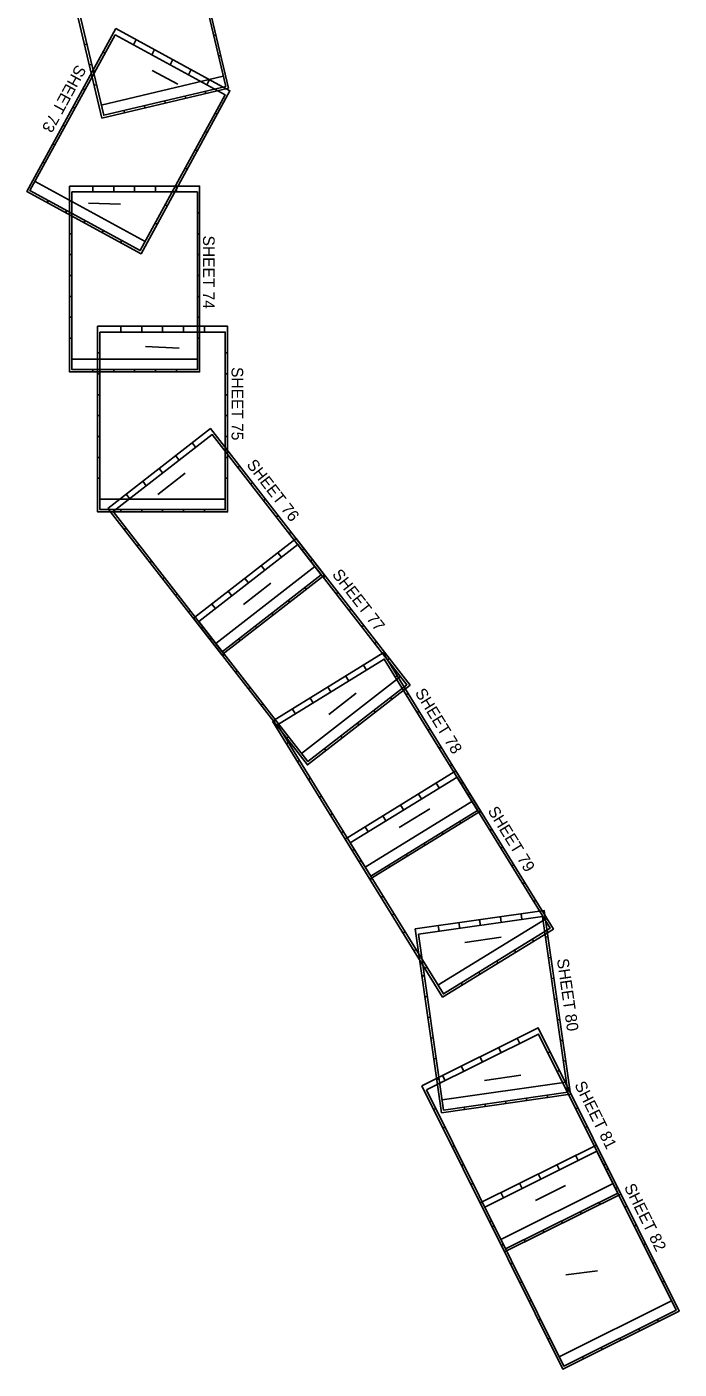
# Model space of a CAD drawing. Extents: x 518852 to 589310, y 1937169 to 2155394.
# Drawn here: x 575262 to 589310, y 1937169 to 1966083 of the extents above; entities that cross this region are included whole.
import ezdxf

# ---------------------------------------------------------------- set-up
doc = ezdxf.new("R2010")
doc.units = 0
doc.layers.add('Level 1', color=7, linetype='Continuous')
doc.layers.add('Level 58', color=7, linetype='Continuous')

msp = doc.modelspace()

# ---------------------------------------------------------------- linework, layer by layer
at = {"layer": 'Level 1'}
for p, q in [((579285, 1965896), (579334, 1965907)), ((576505, 1965700), (576554, 1965711)), ((577556, 1965698), (577616, 1965808)), ((576901, 1965542), (576945, 1965518)), ((577951, 1965483), (578011, 1965593)), ((578346, 1965267), (578406, 1965377)), ((579389, 1965458), (579437, 1965469)), ((576609, 1965262), (576658, 1965273)), ((576686, 1965147), (576730, 1965123)), ((578741, 1965052), (578801, 1965162)), ((576471, 1964752), (576515, 1964728)), ((576713, 1964824), (576761, 1964835)), ((579492, 1965020), (576865, 1964398)), ((579136, 1964837), (579196, 1964947)), ((578242, 1964441), (578231, 1964490)), ((578680, 1964545), (578669, 1964594)), ((579118, 1964649), (579106, 1964697)), ((576255, 1964357), (576299, 1964333)), ((577366, 1964234), (577355, 1964282)), ((577804, 1964337), (577793, 1964386)), ((579316, 1964226), (579360, 1964202)), ((576040, 1963962), (576084, 1963938)), ((579101, 1963831), (579145, 1963807)), ((575825, 1963567), (575869, 1963543)), ((578885, 1963436), (578929, 1963412)), ((575609, 1963172), (575653, 1963148)), ((578670, 1963041), (578714, 1963017)), ((577809, 1961460), (575438, 1962753)), ((576684, 1962527), (576684, 1962652)), ((577134, 1962527), (577134, 1962652)), ((577584, 1962527), (577584, 1962652)), ((578034, 1962527), (578034, 1962652)), ((578455, 1962646), (578499, 1962622)), ((578484, 1962527), (578484, 1962652)), ((575701, 1962296), (575725, 1962340)), ((578239, 1962251), (578283, 1962227)), ((576096, 1962080), (576120, 1962124)), ((576184, 1962077), (576234, 1962077)), ((576492, 1961865), (576515, 1961909)), ((578024, 1961856), (578068, 1961832)), ((578934, 1962077), (578984, 1962077)), ((576184, 1961627), (576234, 1961627)), ((576887, 1961650), (576911, 1961694)), ((578934, 1961627), (578984, 1961627)), ((577282, 1961434), (577306, 1961478)), ((576184, 1961177), (576234, 1961177)), ((578934, 1961177), (578984, 1961177)), ((576184, 1960727), (576234, 1960727)), ((578934, 1960727), (578984, 1960727)), ((576184, 1960277), (576234, 1960277)), ((578934, 1960277), (578984, 1960277)), ((576184, 1959827), (576234, 1959827)), ((578934, 1959827), (578984, 1959827)), ((577286, 1959510), (577286, 1959635)), ((577736, 1959510), (577736, 1959635)), ((578186, 1959510), (578186, 1959635)), ((578636, 1959510), (578636, 1959635)), ((579086, 1959510), (579086, 1959635)), ((576184, 1959377), (576234, 1959377)), ((578934, 1959377), (578984, 1959377)), ((576786, 1959060), (576836, 1959060)), ((579536, 1959060), (579586, 1959060)), ((578934, 1958927), (576234, 1958927)), ((576684, 1958652), (576684, 1958702)), ((577134, 1958652), (577134, 1958702)), ((577584, 1958652), (577584, 1958702)), ((578034, 1958652), (578034, 1958702)), ((578484, 1958652), (578484, 1958702)), ((576786, 1958610), (576836, 1958610)), ((579536, 1958610), (579586, 1958610)), ((576786, 1958160), (576836, 1958160)), ((579536, 1958160), (579586, 1958160)), ((576786, 1957710), (576836, 1957710)), ((579536, 1957710), (579586, 1957710)), ((576786, 1957260), (576836, 1957260)), ((579536, 1957260), (579586, 1957260)), ((578899, 1957024), (578823, 1957123)), ((579531, 1956945), (579570, 1956976)), ((576786, 1956810), (576836, 1956810)), ((578544, 1956748), (578467, 1956847)), ((579536, 1956810), (579586, 1956810)), ((576786, 1956360), (576836, 1956360)), ((578189, 1956472), (578112, 1956571)), ((579536, 1956360), (579586, 1956360)), ((579807, 1956590), (579846, 1956621)), ((577833, 1956196), (577757, 1956294)), ((580083, 1956235), (580123, 1956265)), ((579536, 1955910), (576836, 1955910)), ((577478, 1955919), (577401, 1956018)), ((580359, 1955879), (580399, 1955910)), ((577286, 1955635), (577286, 1955685)), ((577736, 1955635), (577736, 1955685)), ((578186, 1955635), (578186, 1955685)), ((578636, 1955635), (578636, 1955685)), ((579086, 1955635), (579086, 1955685)), ((580635, 1955524), (580675, 1955555)), ((577360, 1955257), (577399, 1955288)), ((580912, 1955169), (580951, 1955199)), ((577636, 1954902), (577675, 1954933)), ((580743, 1954657), (580667, 1954756)), ((581188, 1954813), (581227, 1954844)), ((577912, 1954547), (577951, 1954577)), ((581464, 1954458), (579332, 1952801)), ((580388, 1954381), (580311, 1954479)), ((581375, 1954578), (581414, 1954608)), ((578188, 1954191), (578228, 1954222)), ((580033, 1954104), (579956, 1954203)), ((581651, 1954222), (581691, 1954253)), ((578464, 1953836), (578504, 1953867)), ((579678, 1953828), (579601, 1953927)), ((581277, 1953965), (581247, 1954004)), ((581927, 1953867), (581967, 1953898)), ((578740, 1953481), (578780, 1953512)), ((579322, 1953552), (579246, 1953651)), ((580922, 1953689), (580892, 1953728)), ((582203, 1953512), (582243, 1953543)), ((580212, 1953136), (580181, 1953176)), ((580567, 1953412), (580536, 1953452)), ((582480, 1953157), (582519, 1953187)), ((579017, 1953126), (579056, 1953156)), ((579204, 1952890), (579243, 1952921)), ((579856, 1952860), (579826, 1952900)), ((582756, 1952801), (582795, 1952832)), ((579480, 1952535), (579519, 1952565)), ((582578, 1952227), (582512, 1952334)), ((583032, 1952446), (583071, 1952477)), ((579756, 1952179), (579796, 1952210)), ((583308, 1952091), (581177, 1950434)), ((582195, 1951992), (582129, 1952098)), ((583197, 1952080), (583239, 1952106)), ((580032, 1951824), (580072, 1951855)), ((581811, 1951756), (581746, 1951862)), ((580308, 1951469), (580348, 1951500)), ((581428, 1951520), (581363, 1951626)), ((583122, 1951597), (583091, 1951637)), ((583433, 1951697), (583475, 1951723)), ((581045, 1951284), (580979, 1951390)), ((582766, 1951321), (582736, 1951361)), ((583669, 1951314), (583711, 1951340)), ((580585, 1951114), (580624, 1951144)), ((582411, 1951045), (582380, 1951085)), ((583905, 1950931), (583947, 1950957)), ((580855, 1950638), (580898, 1950665)), ((580861, 1950758), (580900, 1950789)), ((582056, 1950769), (582025, 1950808)), ((584141, 1950547), (584183, 1950574)), ((581091, 1950255), (581134, 1950281)), ((581701, 1950493), (581670, 1950532)), ((584376, 1950164), (584419, 1950190)), ((581327, 1949872), (581370, 1949898)), ((584143, 1949688), (584078, 1949794)), ((584612, 1949781), (584655, 1949807)), ((581563, 1949489), (581605, 1949515)), ((583760, 1949452), (583695, 1949558)), ((584763, 1949540), (584805, 1949567)), ((581799, 1949106), (581841, 1949132)), ((584848, 1949398), (582549, 1947982)), ((583377, 1949216), (583311, 1949322)), ((584998, 1949157), (585041, 1949183)), ((582611, 1948744), (582545, 1948850)), ((582994, 1948980), (582928, 1949086)), ((584609, 1948928), (584583, 1948970)), ((582035, 1948722), (582077, 1948749)), ((584226, 1948692), (584200, 1948734)), ((585234, 1948774), (585277, 1948800)), ((582271, 1948339), (582313, 1948365)), ((583460, 1948220), (583434, 1948263)), ((583843, 1948456), (583817, 1948498)), ((585470, 1948391), (585513, 1948417)), ((582421, 1948099), (582463, 1948125)), ((583077, 1947984), (583050, 1948027)), ((585706, 1948008), (585749, 1948034)), ((582657, 1947715), (582699, 1947742)), ((585942, 1947624), (585985, 1947651)), ((582893, 1947332), (582935, 1947358)), ((586178, 1947241), (586221, 1947267)), ((583129, 1946949), (583171, 1946975)), ((586414, 1946858), (584115, 1945443)), ((585032, 1946727), (585014, 1946851)), ((585477, 1946791), (585460, 1946914)), ((585923, 1946854), (585905, 1946978)), ((583364, 1946566), (583407, 1946592)), ((584141, 1946599), (584123, 1946723)), ((584587, 1946663), (584569, 1946787)), ((586175, 1946388), (586149, 1946431)), ((586432, 1946473), (586482, 1946480)), ((583600, 1946183), (583643, 1946209)), ((583710, 1946083), (583759, 1946090)), ((585409, 1945916), (585382, 1945959)), ((585792, 1946152), (585766, 1946195)), ((586496, 1946027), (586545, 1946034)), ((583836, 1945799), (583879, 1945826)), ((585025, 1945680), (584999, 1945723)), ((583774, 1945638), (583823, 1945645)), ((584642, 1945444), (584616, 1945487)), ((586560, 1945582), (586609, 1945589)), ((583837, 1945192), (583887, 1945199)), ((586623, 1945136), (586673, 1945143)), ((583901, 1944747), (583951, 1944754)), ((586687, 1944691), (586737, 1944698)), ((583965, 1944301), (584014, 1944308)), ((585881, 1944187), (585825, 1944299)), ((586751, 1944245), (586800, 1944252)), ((585478, 1943987), (585422, 1944099)), ((586484, 1943985), (586529, 1944007)), ((584029, 1943856), (584078, 1943863)), ((584672, 1943586), (584616, 1943698)), ((585075, 1943787), (585019, 1943898)), ((586815, 1943800), (586864, 1943807)), ((584092, 1943410), (584142, 1943417)), ((586878, 1943354), (584206, 1942972)), ((584269, 1943386), (584213, 1943498)), ((586685, 1943582), (586729, 1943604)), ((586472, 1943018), (586465, 1943068)), ((586885, 1943179), (586930, 1943201)), ((584022, 1942760), (584067, 1942782)), ((584690, 1942763), (584683, 1942813)), ((585136, 1942827), (585129, 1942877)), ((585581, 1942891), (585574, 1942940)), ((586027, 1942955), (586019, 1943004)), ((587085, 1942776), (587130, 1942798)), ((584222, 1942357), (584267, 1942380)), ((587286, 1942373), (587331, 1942396)), ((584423, 1941954), (584468, 1941977)), ((587486, 1941970), (587531, 1941993)), ((587137, 1941663), (587081, 1941775)), ((584623, 1941551), (584668, 1941574)), ((586331, 1941262), (586275, 1941374)), ((586734, 1941462), (586678, 1941574)), ((587687, 1941567), (587731, 1941590)), ((587740, 1941460), (587785, 1941483)), ((584824, 1941149), (584868, 1941171)), ((587887, 1941165), (585470, 1939962)), ((585928, 1941062), (585872, 1941173)), ((587940, 1941057), (587985, 1941080)), ((585024, 1940746), (585069, 1940768)), ((585525, 1940861), (585469, 1940973)), ((587607, 1940718), (587584, 1940763)), ((587204, 1940518), (587181, 1940562)), ((588141, 1940655), (588186, 1940677)), ((585224, 1940343), (585269, 1940365)), ((585278, 1940236), (585323, 1940258)), ((586398, 1940117), (586376, 1940161)), ((586801, 1940317), (586779, 1940362)), ((588341, 1940252), (588386, 1940274)), ((585995, 1939916), (585973, 1939961)), ((588542, 1939849), (588586, 1939871)), ((585478, 1939833), (585523, 1939855)), ((585679, 1939430), (585723, 1939452)), ((588742, 1939446), (588787, 1939468)), ((585879, 1939027), (585924, 1939049)), ((588943, 1939043), (588987, 1939065)), ((586079, 1938624), (586124, 1938646)), ((589143, 1938640), (586725, 1937437)), ((586280, 1938221), (586325, 1938243)), ((588862, 1938193), (588840, 1938238)), ((588460, 1937993), (588437, 1938038)), ((586480, 1937818), (586525, 1937840)), ((587654, 1937592), (587632, 1937637)), ((588057, 1937793), (588034, 1937837)), ((587251, 1937392), (587229, 1937436))]:
    msp.add_line(p, q, dxfattribs=at)
for points in [[(575958, 1968011), (576880, 1964118), (579604, 1964764), (578682, 1968656)], [(576035, 1967901), (576917, 1964179), (579544, 1964801), (578663, 1968523)], [(577177, 1966047), (575262, 1962535), (577721, 1961195), (579635, 1964707)], [(577161, 1965914), (575330, 1962555), (577701, 1961263), (579531, 1964621)], [(576184, 1962652), (576184, 1958652), (578984, 1958652), (578984, 1962652)], [(576234, 1962527), (576234, 1958702), (578934, 1958702), (578934, 1962527)], [(576786, 1959635), (576786, 1955635), (579586, 1955635), (579586, 1959635)], [(576836, 1959510), (576836, 1955685), (579536, 1955685), (579536, 1959510)], [(577007, 1955711), (579462, 1952553), (581672, 1954272), (579217, 1957430)], [(577123, 1955643), (579470, 1952623), (581602, 1954281), (579255, 1957300)], [(578851, 1953344), (581306, 1950186), (583516, 1951904), (581061, 1955062)], [(578967, 1953276), (581315, 1950256), (583446, 1951913), (581099, 1954933)], [(580554, 1951128), (582651, 1947722), (585035, 1949190), (582938, 1952596)], [(580662, 1951048), (582667, 1947791), (584966, 1949206), (582961, 1952463)], [(582119, 1948588), (584216, 1945182), (586601, 1946650), (584504, 1950056)], [(582227, 1948508), (584233, 1945251), (586532, 1946666), (584527, 1949924)], [(583628, 1946652), (584195, 1942693), (586967, 1943089), (586400, 1947049)], [(583696, 1946536), (584238, 1942749), (586910, 1943132), (586368, 1946918)], [(583766, 1943275), (585547, 1939694), (588054, 1940941), (586273, 1944522)], [(583866, 1943185), (585570, 1939761), (587987, 1940963), (586284, 1944388)], [(585022, 1940750), (586803, 1937169), (589310, 1938416), (587529, 1941997)], [(585122, 1940661), (586826, 1937236), (589243, 1938439), (587540, 1941863)]]:
    msp.add_lwpolyline(points, close=True, dxfattribs=at)
at = {"layer": 'Level 58'}
for p, q in [((577962, 1965146), (578513, 1964846)), ((576589, 1962288), (577276, 1962264)), ((577820, 1959195), (578546, 1959163)), ((578083, 1956010), (578672, 1956468)), ((579925, 1953642), (580514, 1954099)), ((581766, 1951273), (582355, 1951731)), ((583283, 1948837), (583940, 1949241)), ((584692, 1946359), (585476, 1946471)), ((585117, 1943389), (585901, 1943502)), ((586217, 1940803), (586866, 1941126)), ((586868, 1939200), (587554, 1939289))]:
    msp.add_line(p, q, dxfattribs=at)

# ---------------------------------------------------------------- texts
for s, rotation, p in [('SHEET 73', 241.4075, (576334, 1965286)), ('SHEET 74', 270.0001, (579056, 1961587)), ('SHEET 75', 270.0001, (579671, 1958755)), ('SHEET 76', 307.8606, (579982, 1956649)), ('SHEET 77', 307.8606, (581825, 1954284)), ('SHEET 78', 301.6197, (583612, 1951740)), ('SHEET 79', 301.6197, (585179, 1949197)), ('SHEET 80', 278.1456, (586677, 1945998)), ('SHEET 81', 296.4469, (587049, 1943297)), ('SHEET 82', 296.4469, (588118, 1941093))]:
    msp.add_text(s, height=250, rotation=rotation, dxfattribs=at).set_placement(p)

doc.saveas('drawing.dxf')
